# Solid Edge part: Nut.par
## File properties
Author: Sarvanan
Template: sync iso part.par
Last saved by: Cadcim
Revision: 8
Application: Solid Edge
Accuracy: 0.990
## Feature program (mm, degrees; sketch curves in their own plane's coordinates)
sketch for "Hole_1" plane through (21.0838, 43.6973, 12) normal (0, 0, 1) x-axis (1, 0, 0)
  hole centre (-1.3414, 0.2221) bore radius 6
hole "Hole_1" diameter 12 through
pattern "unnamed Pattern 1" of "Hole_1"
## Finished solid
Body 1: solid body, 21 faces, 56 edges, 36 vertices.
  Faces by surface: spun 12, plane 8, cylinder 1
  Edges by curve: circle 18, line 18, intersection 17, spline 3
Bounding box of the edges (mm; curved faces can reach further): 30.022 x 26.000 x 12.000, from (4.7313, 30.9194, 0) to (34.7535, 56.9194, 12).
Cylindrical faces by radius (mm): R6 x1
Planar faces by outward normal: +y 1, +z 1, -y 1, -z 1, oblique 4
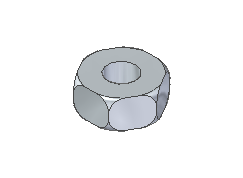
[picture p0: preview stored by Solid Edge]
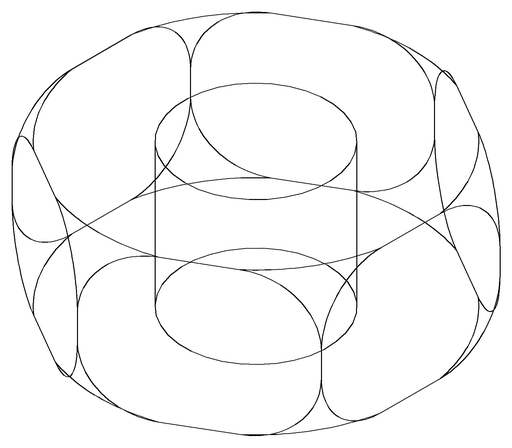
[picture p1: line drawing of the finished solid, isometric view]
